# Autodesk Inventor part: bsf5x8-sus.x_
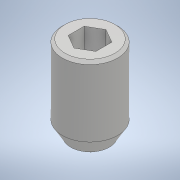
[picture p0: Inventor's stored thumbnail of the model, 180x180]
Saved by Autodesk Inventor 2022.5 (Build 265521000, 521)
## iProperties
Created: 2020-01
Part Number: bsf5x8-sus.x_
Material: 一般
Document SubType Name: Modeling
Designer: ImaoCorp
Density: 1 g/cm^3
Appearance: 既定
Sending System: SOLIDWORKS 2018-2018316
MC: AMD64
MC_MODEL: Intel64 Family 6 Model 60 Stepping 3, GenuineIntel
OS: Windows_NT
FRU: Parasolid Version 30.0, build 310,  6- 8-2018
FORMAT: text
GUISE: transmit
KEY: bsf5x8-sus
FILE: bsf5x8-sus.x_t
DATE: Thu Jan 23 16:48:38 2020
Author: ImaoCorp
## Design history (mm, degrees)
feature "Base1"
node "ソリッド1"
